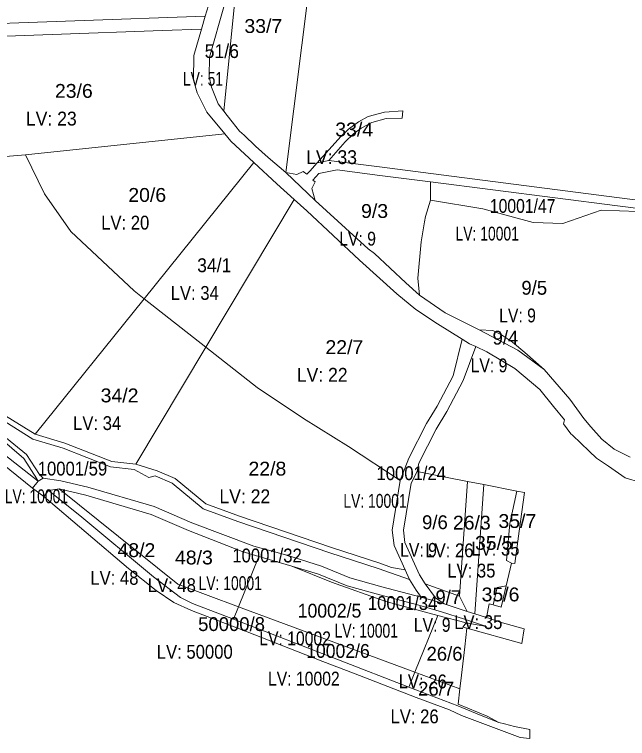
# Model space of a CAD drawing. Extents: x -713758 to -711119, y -1123067 to -1120789.
# Drawn here: x -712790 to -712347, y -1122720 to -1122197 of the extents above; entities that cross this region are included whole.
import ezdxf
from ezdxf.enums import TextEntityAlignment as Align

# ---------------------------------------------------------------- set-up
doc = ezdxf.new("R2010")
doc.units = 0
doc.header["$LTSCALE"] = 4
doc.layers.add('10', color=7, linetype='Continuous', lineweight=13)
doc.layers.add('11', color=7, linetype='Continuous')
doc.layers.add('13', color=7, linetype='Continuous')

msp = doc.modelspace()

# ---------------------------------------------------------------- linework, layer by layer
at = {"layer": '10'}
for points in [[(-712638.37, -1122267.02), (-712626.26, -1122145.69), (-712624.64, -1122135.22), (-712614.24, -1122132.63), (-712589.67, -1122129.53), (-712583.46, -1122128.75), (-712570.37, -1122127.1), (-712593.46, -1122311.4), (-712606.26, -1122300.57), (-712615.39, -1122292.19), (-712623.54, -1122284.42), (-712626.92, -1122281.37), (-712632.38, -1122274.66), (-712635.85, -1122270.26)], [(-712648.93, -1122241.9), (-712647.32, -1122249.66), (-712642.44, -1122261.77), (-712638.37, -1122267.02), (-712626.26, -1122145.69), (-712637.78, -1122190), (-712648.55, -1122227.95)], [(-713028.86, -1122212.11), (-712840.29, -1122205.23), (-712651.72, -1122198.35), (-712648.29, -1122186.66), (-712641.22, -1122161.19), (-712831.84, -1122168.14), (-713022.45, -1122175.1), (-713025.76, -1122188.12), (-713028.85, -1122211.11)], [(-713028.91, -1122221.35), (-712842.39, -1122214.55), (-712682.59, -1122208.72), (-712654.45, -1122207.69), (-712651.72, -1122198.35), (-712840.29, -1122205.23), (-713028.86, -1122212.11)], [(-712842.39, -1122214.55), (-712682.59, -1122208.72), (-712654.45, -1122207.69), (-712660.03, -1122226.71), (-712660.27, -1122244.45), (-712657.62, -1122253.69), (-712650.61, -1122267.8), (-712637.62, -1122283.48), (-712781.58, -1122298.68), (-712831.54, -1122302.56), (-712841.94, -1122220.03)], [(-712570.89, -1122304.44), (-712562.52, -1122302.63), (-712550.69, -1122289.18), (-712544.6, -1122283.32), (-712539.11, -1122279.24), (-712531.35, -1122275.19), (-712520.91, -1122272.33), (-712509.45, -1122272.01), (-712508.97, -1122266.83), (-712522.23, -1122267.69), (-712533.95, -1122270.96), (-712540.95, -1122274.63), (-712548.16, -1122279.95), (-712553.82, -1122285.34)], [(-712781.58, -1122298.68), (-712637.62, -1122283.48), (-712633.24, -1122288.76), (-712629.93, -1122291.87), (-712616.65, -1122304.13), (-712695.91, -1122402.6), (-712703.17, -1122396.9), (-712748.89, -1122353.98), (-712767.93, -1122326.7)], [(-712899.9, -1122310.71), (-712831.54, -1122302.56), (-712781.58, -1122298.68), (-712767.93, -1122326.7), (-712748.89, -1122353.98), (-712703.17, -1122396.9), (-712695.91, -1122402.6), (-712774.62, -1122500.39), (-712799.12, -1122485.22), (-712813.16, -1122473.21), (-712829.61, -1122456.21), (-712862.21, -1122430.51), (-712872.38, -1122420.97), (-712878.07, -1122408.41), (-712885.9, -1122382.52), (-712891.47, -1122360.38), (-712894.85, -1122342.83), (-712896.75, -1122315.98)], [(-712695.91, -1122402.6), (-712651.34, -1122437.58), (-712587.4, -1122330.88), (-712599.9, -1122319.58), (-712616.65, -1122304.13)], [(-712574.71, -1122322.82), (-712572.25, -1122331.55), (-712534.09, -1122366.41), (-712529.41, -1122369.79), (-712506.87, -1122391), (-712496.96, -1122400.02), (-712498.06, -1122387.63), (-712495.71, -1122361.53), (-712493.27, -1122347.03), (-712492.48, -1122343.18), (-712489, -1122331.34), (-712488.88, -1122318.12), (-712525.56, -1122313.42), (-712556.39, -1122309.47), (-712569.7, -1122312.11), (-712571.73, -1122314.39), (-712573.89, -1122316.77), (-712572.38, -1122318.19)], [(-712489, -1122331.34), (-712451.14, -1122337.71), (-712414.73, -1122347.45), (-712393.34, -1122348.2), (-712365.63, -1122338.66), (-712339.17, -1122339.5), (-712319.38, -1122341.98), (-712278.52, -1122346.01), (-712278.46, -1122345.56), (-712317.59, -1122340.09), (-712353.76, -1122335.44), (-712488.88, -1122318.12)], [(-712651.34, -1122437.58), (-712587.4, -1122330.88), (-712578.31, -1122339.1), (-712540.18, -1122374.62), (-712513.29, -1122399.07), (-712499.48, -1122410.27), (-712483.99, -1122420.73), (-712466.15, -1122431.7), (-712472.69, -1122458.35), (-712484.22, -1122480.12), (-712491.94, -1122492.81), (-712504.54, -1122517.81), (-712510.81, -1122534.01), (-712548.12, -1122509.4), (-712580.84, -1122489.15), (-712614.23, -1122466.7)], [(-712774.62, -1122500.39), (-712753.22, -1122506.8), (-712719.18, -1122520.07), (-712701.92, -1122521.99), (-712651.34, -1122437.58), (-712695.91, -1122402.6)], [(-712877.48, -1122421.44), (-712867.93, -1122438.67), (-712831.24, -1122475.24), (-712817.28, -1122490.23), (-712800.46, -1122503.04), (-712782.82, -1122518), (-712773.42, -1122532.7), (-712772.56, -1122534.45), (-712768.79, -1122532.19), (-712771.43, -1122529.55), (-712780.93, -1122515.2), (-712799.18, -1122500.14), (-712815.86, -1122487.57), (-712829.18, -1122472.48), (-712846.59, -1122455.35), (-712862.65, -1122438.97), (-712865.73, -1122436.15), (-712868.55, -1122432.16)], [(-712453.87, -1122425.02), (-712425.88, -1122439.83), (-712406.72, -1122453.8), (-712420.87, -1122441.5), (-712429.67, -1122433.88), (-712437.73, -1122428.69), (-712443.83, -1122425.6)], [(-712516.63, -1122569.68), (-712510.81, -1122534.01), (-712504.54, -1122517.81), (-712491.94, -1122492.81), (-712484.22, -1122480.12), (-712472.69, -1122458.35), (-712466.15, -1122431.7), (-712460.72, -1122435.04), (-712456.17, -1122437.14), (-712465.38, -1122461.65), (-712477.25, -1122484.06), (-712484.94, -1122496.69), (-712497.4, -1122521.41), (-712498.51, -1122527.43), (-712503.01, -1122535.91), (-712508.55, -1122569.83), (-712507.43, -1122578.75), (-712496.83, -1122602.09), (-712492.74, -1122608.59), (-712485.26, -1122618.79), (-712479.17, -1122622.97), (-712495.68, -1122618.11), (-712499.38, -1122613.06), (-712504.15, -1122605.32), (-712507.33, -1122598.33), (-712515.22, -1122580.95)], [(-712701.92, -1122521.99), (-712651.34, -1122437.58), (-712614.23, -1122466.7), (-712580.84, -1122489.15), (-712548.12, -1122509.4), (-712510.81, -1122534.01), (-712516.63, -1122569.68), (-712515.22, -1122580.95), (-712507.33, -1122598.33), (-712517.02, -1122596.65), (-712525.59, -1122593.7), (-712560.57, -1122582.38), (-712626.96, -1122559.79), (-712651.26, -1122550.83), (-712673.54, -1122532.35), (-712686.39, -1122526.85)], [(-712508.55, -1122569.83), (-712507.43, -1122578.75), (-712496.83, -1122602.09), (-712492.74, -1122608.59), (-712467.98, -1122617.46), (-712462.16, -1122534.55), (-712478.19, -1122531.41), (-712498.51, -1122527.43), (-712503.01, -1122535.91)], [(-712776.53, -1122539.37), (-712768.37, -1122545.57), (-712765.06, -1122541.14), (-712757.19, -1122539.98), (-712738.02, -1122544.43), (-712690.74, -1122558.45), (-712663.92, -1122570.01), (-712625.1, -1122585.15), (-712613.09, -1122588.7), (-712589.15, -1122595.77), (-712569.85, -1122601.51), (-712549.18, -1122609.97), (-712525.58, -1122616.44), (-712497.29, -1122623.89), (-712480.98, -1122628.69), (-712464.42, -1122634.18), (-712448.54, -1122639.31), (-712463.14, -1122636.83), (-712465.67, -1122639.8), (-712462.63, -1122640.67), (-712422.96, -1122651.62), (-712421.18, -1122641.14), (-712438.7, -1122636.18), (-712445.98, -1122633.66), (-712448.54, -1122632.86), (-712456.88, -1122630.25), (-712462.53, -1122628.48), (-712479.17, -1122622.97), (-712495.68, -1122618.11), (-712524.01, -1122610.65), (-712547.24, -1122604.28), (-712567.8, -1122595.87), (-712592.88, -1122587.84), (-712616.56, -1122581.36), (-712661.54, -1122564.5), (-712688.69, -1122552.8), (-712736.5, -1122538.62), (-712756.06, -1122534.08), (-712768.79, -1122532.19), (-712772.56, -1122534.45)], [(-712467.98, -1122617.46), (-712462.53, -1122628.48), (-712456.88, -1122630.25), (-712450.34, -1122536.87), (-712462.16, -1122534.55)], [(-712765.06, -1122541.14), (-712757.19, -1122539.98), (-712671.46, -1122608.92), (-712627.74, -1122625.14), (-712631.37, -1122634.17), (-712660.92, -1122622.73), (-712669.73, -1122618.43), (-712689.24, -1122603.58), (-712742.4, -1122559.19)], [(-712757.19, -1122539.98), (-712738.02, -1122544.43), (-712690.74, -1122558.45), (-712663.92, -1122570.01), (-712625.1, -1122585.15), (-712613.09, -1122588.7), (-712627.74, -1122625.14), (-712671.46, -1122608.92)], [(-712456.88, -1122630.25), (-712448.54, -1122632.86), (-712446.47, -1122623.04), (-712443.67, -1122623.8), (-712440.79, -1122611.33), (-712434.25, -1122609.96), (-712430.47, -1122593.67), (-712433.99, -1122591.74), (-712431.66, -1122564.88), (-712426.59, -1122541.52), (-712450.34, -1122536.87)], [(-712768.37, -1122545.57), (-712707.17, -1122597.46), (-712687.31, -1122613.35), (-712674.54, -1122622.17), (-712661.73, -1122627.77), (-712622.56, -1122642.65), (-712566.7, -1122664.71), (-712544.48, -1122673.18), (-712499.25, -1122690.74), (-712475.21, -1122699.53), (-712466.54, -1122703.69), (-712424.15, -1122719.65), (-712417.16, -1122720.34), (-712417.25, -1122713.84), (-712428.21, -1122711.71), (-712435.37, -1122709.72), (-712439.45, -1122708.69), (-712452.27, -1122703.59), (-712469.26, -1122696.73), (-712504.54, -1122683.17), (-712555.41, -1122663.57), (-712631.37, -1122634.17), (-712660.92, -1122622.73), (-712669.73, -1122618.43), (-712689.24, -1122603.58), (-712742.4, -1122559.19), (-712765.06, -1122541.14)], [(-712433.99, -1122591.74), (-712430.47, -1122593.67), (-712428.09, -1122593.99), (-712424.76, -1122570.5), (-712420.91, -1122542.63), (-712426.59, -1122541.52), (-712431.66, -1122564.88)], [(-712627.74, -1122625.14), (-712613.09, -1122588.7), (-712589.15, -1122595.77), (-712560.47, -1122607.44), (-712521.31, -1122621.32), (-712483.71, -1122631.39), (-712500.22, -1122672.44)], [(-712589.15, -1122595.77), (-712560.47, -1122607.44), (-712521.31, -1122621.32), (-712483.71, -1122631.39), (-712463.14, -1122636.83), (-712448.54, -1122639.31), (-712464.42, -1122634.18), (-712480.98, -1122628.69), (-712497.29, -1122623.89), (-712525.58, -1122616.44), (-712549.18, -1122609.97), (-712569.85, -1122601.51)], [(-712492.74, -1122608.59), (-712485.26, -1122618.79), (-712479.17, -1122622.97), (-712462.53, -1122628.48), (-712467.98, -1122617.46)], [(-712443.67, -1122623.8), (-712437.8, -1122625.38), (-712434.25, -1122609.96), (-712440.79, -1122611.33)], [(-712631.37, -1122634.17), (-712627.74, -1122625.14), (-712500.22, -1122672.44), (-712504.54, -1122683.17), (-712555.41, -1122663.57)], [(-712500.22, -1122672.44), (-712483.71, -1122631.39), (-712463.14, -1122636.83), (-712465.67, -1122639.8), (-712462.63, -1122640.67), (-712464.15, -1122654.16), (-712466.62, -1122674.45), (-712467.75, -1122684.48)], [(-712504.54, -1122683.17), (-712500.22, -1122672.44), (-712467.75, -1122684.48), (-712469, -1122695.49), (-712448.05, -1122704.24), (-712439.45, -1122708.69), (-712452.27, -1122703.59), (-712469.26, -1122696.73)]]:
    msp.add_lwpolyline(points, close=True, dxfattribs=at)
for points in [[(-712316.81, -1122334.14), (-712352.47, -1122329.56), (-712488.83, -1122312.08), (-712523.9, -1122307.58), (-712562.52, -1122302.63), (-712550.69, -1122289.18), (-712544.6, -1122283.32), (-712539.11, -1122279.24), (-712531.35, -1122275.19), (-712520.91, -1122272.33), (-712509.45, -1122272.01), (-712508.97, -1122266.83), (-712522.23, -1122267.69), (-712533.95, -1122270.96), (-712540.95, -1122274.63), (-712548.16, -1122279.95), (-712553.82, -1122285.34), (-712570.89, -1122304.44), (-712576.21, -1122310.4), (-712578.26, -1122312.66), (-712580.9, -1122310.59), (-712585.56, -1122312.9), (-712593.46, -1122311.4), (-712570.37, -1122127.1)], [(-712648.29, -1122186.66), (-712651.72, -1122198.35), (-712654.45, -1122207.69), (-712660.03, -1122226.71), (-712660.27, -1122244.45), (-712657.62, -1122253.69), (-712650.61, -1122267.8), (-712637.62, -1122283.48), (-712633.24, -1122288.76), (-712629.93, -1122291.87), (-712616.65, -1122304.13), (-712599.9, -1122319.58), (-712587.4, -1122330.88), (-712578.31, -1122339.1), (-712540.18, -1122374.62), (-712513.29, -1122399.07), (-712499.48, -1122410.27), (-712483.99, -1122420.73), (-712466.15, -1122431.7), (-712460.72, -1122435.04), (-712456.17, -1122437.14), (-712448.14, -1122440.84), (-712427.92, -1122452.87), (-712409.89, -1122468.24), (-712399.98, -1122480.38), (-712392.15, -1122490.11), (-712392.86, -1122492.94), (-712387.54, -1122500.22), (-712386.28, -1122501.06), (-712374.31, -1122512.74), (-712368.89, -1122517.79), (-712360.4, -1122523.54), (-712348.25, -1122531.87), (-712325.6, -1122538.69)], [(-712623.54, -1122284.42), (-712626.92, -1122281.37), (-712632.38, -1122274.66), (-712635.85, -1122270.26), (-712638.37, -1122267.02), (-712642.44, -1122261.77), (-712647.32, -1122249.66), (-712648.93, -1122241.9), (-712648.55, -1122227.95), (-712637.78, -1122190)], [(-712344.67, -1122516.97), (-712356.28, -1122511.16), (-712365.23, -1122504.09), (-712372.97, -1122495.12), (-712378.16, -1122488.99), (-712388.31, -1122475.04), (-712406.72, -1122453.8), (-712425.88, -1122439.83), (-712453.87, -1122425.02), (-712478.35, -1122412.73), (-712496.96, -1122400.02), (-712506.87, -1122391), (-712529.41, -1122369.79), (-712534.09, -1122366.41), (-712572.25, -1122331.55), (-712593.46, -1122311.4), (-712606.26, -1122300.57), (-712615.39, -1122292.19), (-712623.54, -1122284.42)], [(-712316.81, -1122334.14), (-712352.47, -1122329.56), (-712488.83, -1122312.08), (-712523.9, -1122307.58), (-712562.52, -1122302.63), (-712570.89, -1122304.44), (-712576.21, -1122310.4), (-712578.26, -1122312.66), (-712580.9, -1122310.59), (-712585.56, -1122312.9), (-712593.46, -1122311.4), (-712572.25, -1122331.55), (-712574.71, -1122322.82), (-712572.38, -1122318.19), (-712573.89, -1122316.77), (-712571.73, -1122314.39), (-712569.7, -1122312.11), (-712556.39, -1122309.47), (-712525.56, -1122313.42), (-712488.88, -1122318.12), (-712353.76, -1122335.44), (-712317.59, -1122340.09)], [(-712339.17, -1122339.5), (-712365.63, -1122338.66), (-712393.34, -1122348.2), (-712414.73, -1122347.45), (-712451.14, -1122337.71), (-712489, -1122331.34), (-712492.48, -1122343.18), (-712493.27, -1122347.03), (-712495.71, -1122361.53), (-712498.06, -1122387.63), (-712496.96, -1122400.02), (-712478.35, -1122412.73), (-712453.87, -1122425.02), (-712443.83, -1122425.6), (-712437.73, -1122428.69), (-712429.67, -1122433.88), (-712420.87, -1122441.5), (-712406.72, -1122453.8), (-712388.31, -1122475.04), (-712378.16, -1122488.99), (-712372.97, -1122495.12), (-712365.23, -1122504.09), (-712356.28, -1122511.16), (-712344.67, -1122516.97)], [(-712894.29, -1122438.71), (-712772.56, -1122534.45), (-712773.42, -1122532.7), (-712782.82, -1122518), (-712800.46, -1122503.04)], [(-712827.18, -1122498.66), (-712776.53, -1122539.37), (-712772.56, -1122534.45), (-712894.29, -1122438.71)], [(-712801.49, -1122488.46), (-712776.27, -1122504.07), (-712754.52, -1122510.59), (-712720.15, -1122523.99), (-712703.16, -1122525.88), (-712692.48, -1122531.83), (-712687.96, -1122530.53), (-712675.65, -1122535.8), (-712653.28, -1122554.35), (-712628.3, -1122563.56), (-712561.82, -1122586.18), (-712526.83, -1122597.5), (-712504.15, -1122605.32), (-712507.33, -1122598.33), (-712517.02, -1122596.65), (-712525.59, -1122593.7), (-712560.57, -1122582.38), (-712626.96, -1122559.79), (-712651.26, -1122550.83), (-712673.54, -1122532.35), (-712686.39, -1122526.85), (-712701.92, -1122521.99), (-712719.18, -1122520.07), (-712753.22, -1122506.8), (-712774.62, -1122500.39), (-712799.12, -1122485.22)], [(-712799.18, -1122500.14), (-712780.93, -1122515.2), (-712771.43, -1122529.55), (-712768.79, -1122532.19), (-712756.06, -1122534.08), (-712736.5, -1122538.62), (-712688.69, -1122552.8), (-712661.54, -1122564.5), (-712616.56, -1122581.36), (-712592.88, -1122587.84), (-712567.8, -1122595.87), (-712547.24, -1122604.28), (-712524.01, -1122610.65), (-712495.68, -1122618.11), (-712499.38, -1122613.06), (-712504.15, -1122605.32), (-712526.83, -1122597.5), (-712561.82, -1122586.18), (-712628.3, -1122563.56), (-712653.28, -1122554.35), (-712675.65, -1122535.8), (-712687.96, -1122530.53), (-712692.48, -1122531.83), (-712703.16, -1122525.88), (-712720.15, -1122523.99), (-712754.52, -1122510.59), (-712776.27, -1122504.07), (-712801.49, -1122488.46)]]:
    msp.add_lwpolyline(points, dxfattribs=at)

# ---------------------------------------------------------------- texts
at = {"layer": '11'}
for s, width, p in [('33/7', 1.05, (-712609.77, -1122210.5)), ('51/6', 0.95, (-712639.76, -1122228.61)), ('23/6', 1.05, (-712746.699, -1122257.38)), ('33/4', 1.05, (-712544.081, -1122285.25)), ('20/6', 1.05, (-712693.67, -1122332.55)), ('10001/47', 0.85, (-712422.35, -1122340.49)), ('9/3', 1.05, (-712529.351, -1122344.16)), ('34/1', 0.95, (-712645.23, -1122383.36)), ('22/7', 1.05, (-712551.199, -1122442.52)), ('34/2', 1.05, (-712713.65, -1122477.42)), ('10001/59', 0.9, (-712747.69, -1122530.29)), ('22/8', 1.05, (-712606.809, -1122530.33)), ('10001/24', 0.9, (-712502.87, -1122533.62)), ('26/3', 1.05, (-712459.079, -1122569.36)), ('35/7', 1.05, (-712426.171, -1122568.19)), ('35/5', 1.05, (-712443.13, -1122584)), ('48/2', 1.05, (-712701.48, -1122589.23)), ('48/3', 1.05, (-712659.92, -1122594.54)), ('10001/32', 0.9, (-712607.061, -1122593.07)), ('35/6', 1.05, (-712438.35, -1122621.23)), ('10001/34', 0.9, (-712509.12, -1122627.46)), ('10002/5', 0.95, (-712561.91, -1122632.98)), ('10002/6', 0.95, (-712555.821, -1122662.04))]:
    msp.add_text(s, height=10, dxfattribs=dict(at, width=width)).set_placement(p, align=Align.CENTER)
for s, p in [('9/5', (-712413.96, -1122399.64)), ('9/4', (-712434.809, -1122435.71)), ('9/6', (-712485.75, -1122569.05)), ('9/7', (-712476.081, -1122623.23)), ('50000/8', (-712632.72, -1122642.67)), ('26/6', (-712478.82, -1122664.08)), ('26/7', (-712484.9, -1122689.34))]:
    msp.add_text(s, height=10, dxfattribs=at).set_placement(p, align=Align.CENTER)
at = {"layer": '13'}
for s, width, p in [('LV: 51 ', 0.75, (-712651.973, -1122248.61)), ('LV: 23 ', 0.95, (-712761.221, -1122277.38)), ('LV: 33 ', 0.95, (-712558.671, -1122305.25)), ('LV: 20 ', 0.9, (-712707.891, -1122352.55)), ('LV: 10001 ', 0.75, (-712446.575, -1122360.49)), ('LV: 9 ', 0.85, (-712540.058, -1122364.16)), ('LV: 34 ', 0.9, (-712657.645, -1122403.36)), ('LV: 9 ', 0.85, (-712424.467, -1122419.64)), ('LV: 9 ', 0.85, (-712445.082, -1122455.71)), ('LV: 22 ', 0.95, (-712565.454, -1122462.52)), ('LV: 34 ', 0.9, (-712728.172, -1122497.42)), ('LV: 10001 ', 0.75, (-712772.35, -1122550.29)), ('LV: 22 ', 0.95, (-712621.366, -1122550.33)), ('LV: 10001 ', 0.75, (-712527.664, -1122553.62)), ('LV: 9 ', 0.85, (-712496.022, -1122589.05)), ('LV: 26 ', 0.9, (-712473.602, -1122589.36)), ('LV: 35 ', 0.9, (-712440.358, -1122588.19)), ('LV: 35 ', 0.9, (-712457.753, -1122604)), ('LV: 48 ', 0.9, (-712715.701, -1122609.23)), ('LV: 10001 ', 0.75, (-712632.29, -1122613.07)), ('LV: 48 ', 0.9, (-712674.209, -1122614.54)), ('LV: 9 ', 0.85, (-712486.152, -1122643.23)), ('LV: 35 ', 0.9, (-712452.738, -1122641.23)), ('LV: 10001 ', 0.75, (-712533.981, -1122647.46)), ('LV: 10002 ', 0.85, (-712585.232, -1122652.98)), ('LV: 50000 ', 0.9, (-712657.648, -1122662.67)), ('LV: 10002 ', 0.85, (-712578.908, -1122682.04)), ('LV: 26 ', 0.9, (-712492.907, -1122684.08)), ('LV: 26 ', 0.9, (-712498.786, -1122709.34))]:
    msp.add_text(s, height=10, dxfattribs=dict(at, width=width)).set_placement(p, align=Align.CENTER)

doc.saveas('drawing.dxf')
